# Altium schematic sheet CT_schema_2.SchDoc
size 278 x 236 mm
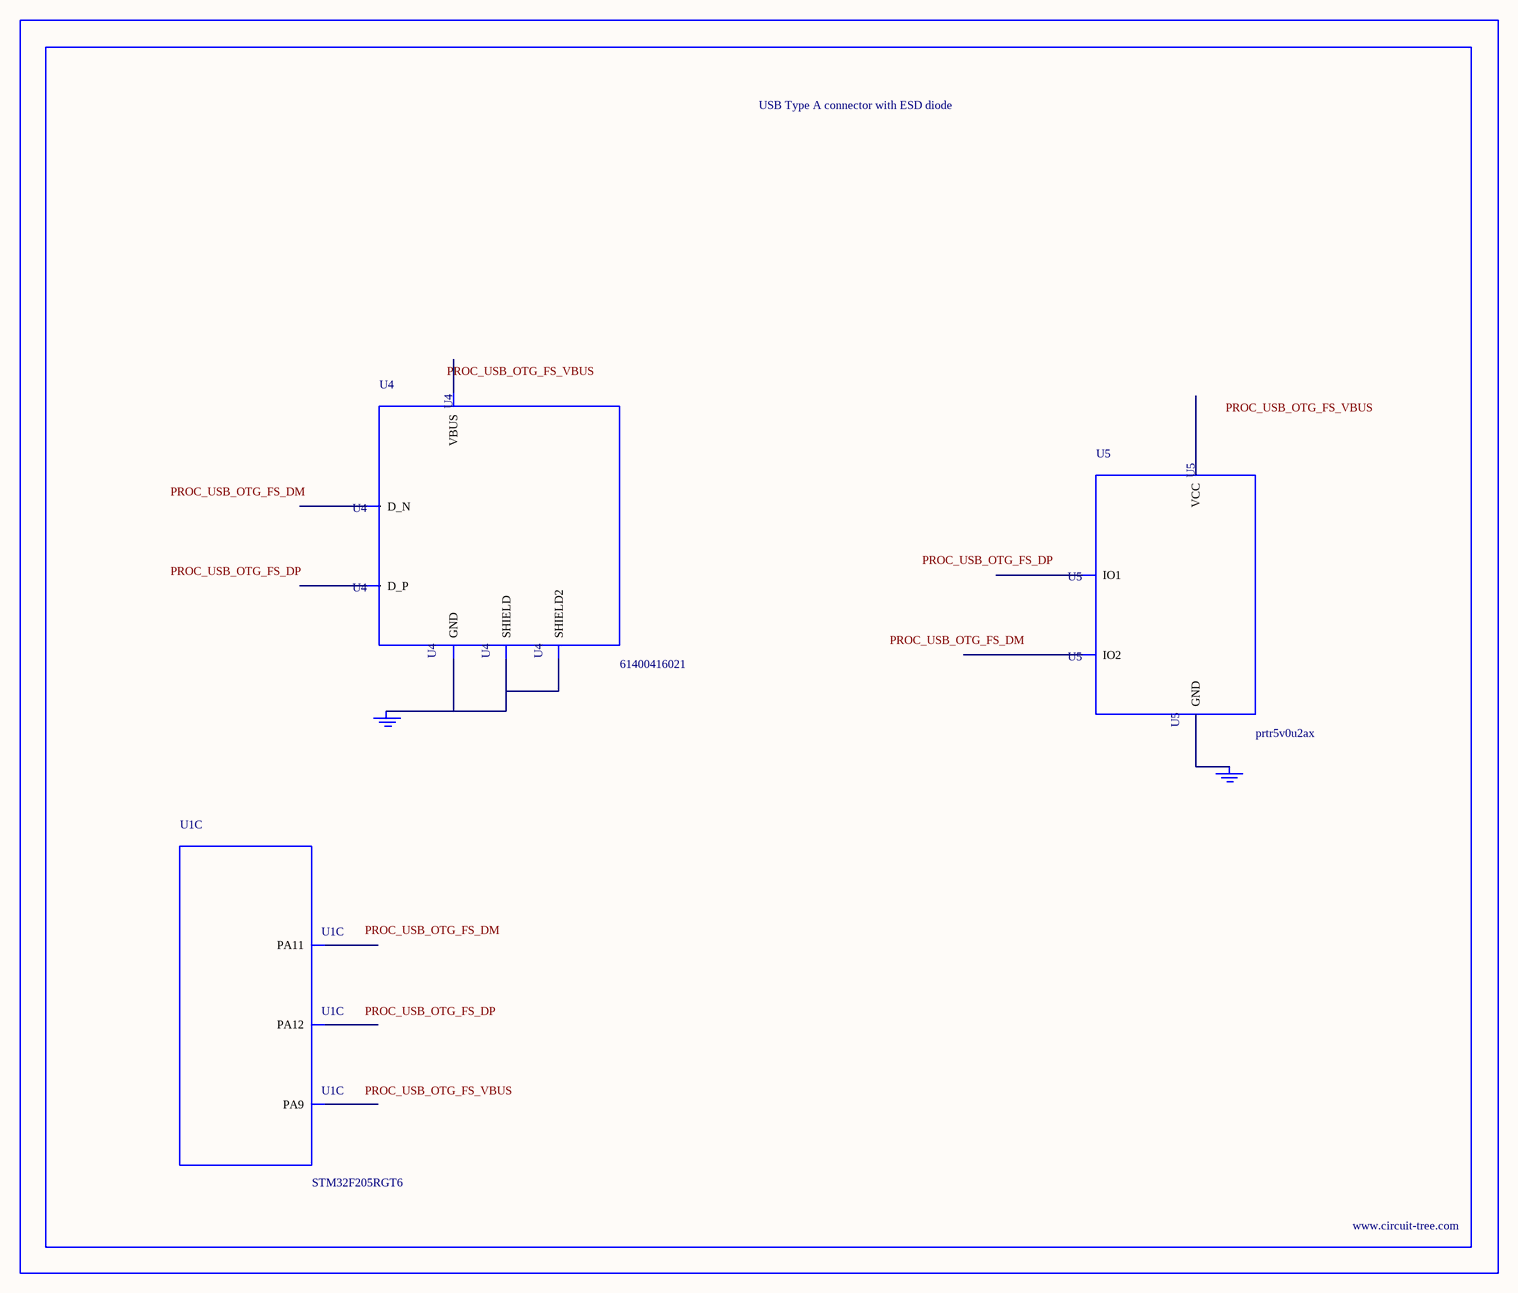
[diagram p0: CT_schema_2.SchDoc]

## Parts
BORDER1  (no value)
GND_INSTANCE_1_0  (no value)
GND_INSTANCE_1_1  (no value)
U1  STM32F205RGT6  [LQFP64]  (part C of 5)
U4  61400416021  [USB-A-H]
U5  prtr5v0u2ax  [SOT143B]

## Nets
NetGND_INSTANCE_1_0_0: GND_INSTANCE_1_0.0(GND) U4.4(GND) U4.5(SHIELD) U4.6(SHIELD2)
NetGND_INSTANCE_1_1_0: GND_INSTANCE_1_1.0(GND) U5.1(GND)

Not connected (* = marked no-connect by the designer): U1 42(PA9) 44(PA11) 45(PA12); U4 1(VBUS) 2(D_N) 3(D_P); U5 2(IO1) 3(IO2) 4(VCC)

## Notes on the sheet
- Labels drawn without touching a wire or pin: PROC_USB_OTG_FS_DM, PROC_USB_OTG_FS_DP, PROC_USB_OTG_FS_VBUS

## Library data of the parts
BORDER1 = BORDER_PAGE1
GND_INSTANCE_1_0 GND_INSTANCE_1_1 = GND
